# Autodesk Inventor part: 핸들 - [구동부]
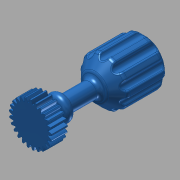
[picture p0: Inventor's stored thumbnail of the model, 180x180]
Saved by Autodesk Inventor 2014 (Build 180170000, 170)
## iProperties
Created: 2017-04
Part Number: 핸들 - [구동부]
Material: 강철, 연강
Document SubType Name: Modeling
Designer: mduedu
Categories: <?xml version="1.0" encoding="UTF-16"?> <MemberInstance><Categories><FamilyTemplate><FamilyTemplateParameter ValueType="xs:double" Id="1" ObjectReferenceKey="da
Density: 1 g/cm^3
Appearance: 청록색
CustomPartVersion: 1
Author: mduedu
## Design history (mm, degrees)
sketch "Sketch1"
  geometry: C1 r 13.5 at (0, 0)
  constraints: 1 centre point
  dimensions: "d0" = 27 diameter of C1 (= da_da)
extrude "Extrusion1" new body sketch "Sketch1" distance "d1" = 10 (= da_b); taper "d2" = 0 deg
workplane "Work Plane2"
sketch "Sketch2"
  geometry: C1 r 13.5 at (0, 0) reference; C2 r 12.5 at (0, 0)
  constraints: 1 centre point, 1 coincident
  dimensions: "d3" = 25 diameter of C2 (= da_dw)
feature "피치 지름" sketch "Sketch2" dims "d4" = 10, "d5" = 0
workplane "Work Plane8"
workplane "Work Plane9"
feature "스퍼 기어" dims "da_b" = 10, "da_d" = 25, "da_aw" = 25, "da_da" = 27, "da_df" = 22.5, "da_dw" = 25, angle "da_beta" = 0 deg, "da_lefttooth" = 0, "da_righttooth" = 0
sketch "스케치3"
  geometry: C1 r 5 at (0, 0); 1 further point
  constraints: 1 centre point, 1 coincident
  dimensions: "d49" = 10 diameter of C1
extrude "돌출2" join sketch "스케치3" distance "d50" = 60; taper "d51" = 0 deg
sketch "스케치4"
  geometry: C1 r 15 at (0, 0); 1 further point
  constraints: 1 centre point, 1 coincident
  dimensions: "d52" = 30 diameter of C1
extrude "돌출3" join sketch "스케치4" distance "d53" = 30; taper "d54" = 0 deg
chamfer "모따기1" distance "d55" = 7; stored, may be unused: second distance "d56" = 2, angle "d57" = 45 deg
sketch "스케치5"
  geometry: L1 (0, 2.2)-(0, -13.2) reference; L2 (0, -5)-(8, -5); L3 (8, -5)-(8, -11); L4 (8, -11)-(0, -11); L5 (0, -11)-(0, -5); 1 further point
  constraints: 8 end point, 2 parallel, 1 horizontal, 1 perpendicular, 1 point on line
  dimensions: "d58" = 5 distance from line of L2 point (0, 0); "d59" = 6 distance of L2.end L3.end; "d60" = 16 diameter of L3 L1
revolve "회전1" sketch "스케치5" stored, may be unused: angle "d61" = 90 deg
fillet "모깎기1" dims "d62" = 3
fillet "모깎기2" dims "d65" = 3
sketch "스케치9"
  geometry: L1 (15, -60)-(-15, -60) reference; L2 (0, -60)-(0, 0); L3 (0, -66.771)-(0, -60); A1 r 20 centre (0, -46.771) between (0, -66.771) and (15, -60)
  constraints: 4 end point, 2 point on circle, 1 centre point, 1 collinear, 1 line through centre, 1 midpoint, 1 perpendicular
  dimensions: "d84" = 20 radius of A1
revolve "회전4" sketch "스케치9" stored, may be unused: angle "d86" = 90 deg
fillet "모깎기3" dims "d72" = 3
sketch "스케치6"
  geometry: C1 r 2.5 at (0, 15); 2 further points
  constraints: 2 vertical alignment, 1 centre point, 1 other
  dimensions: "d66" = 5 diameter of C1
extrude "돌출4" cut sketch "스케치6" stored distance "d67" = 60; taper "d68" = 0 deg
fillet "모깎기4" dims "d73" = 1
node "작업 평면12"
sketch "스케치10"
  geometry: C1 r 6 at (0, 0); 1 further point
  constraints: 1 centre point, 1 coincident
  dimensions: "d87" = 12 diameter of C1
extrude "돌출5" cut sketch "스케치10" distance "d88" = 5; taper "d89" = 0 deg
fillet "모깎기5" dims "d90" = 1
body "Solid1"
pattern_circular "원형 패턴2" dims angle "d75" = 360 deg
body "Srf1"
other parameters: "d16" = 25 (= da_aw), "d17" = 0, "d34" = 1.25664 (computed from da_z), "d39" = 0, "d41" = 0, "d43" = 25 (= da_aw), "d46" = 25 (= da_aw), "d47" = 0, "d48" = 0
